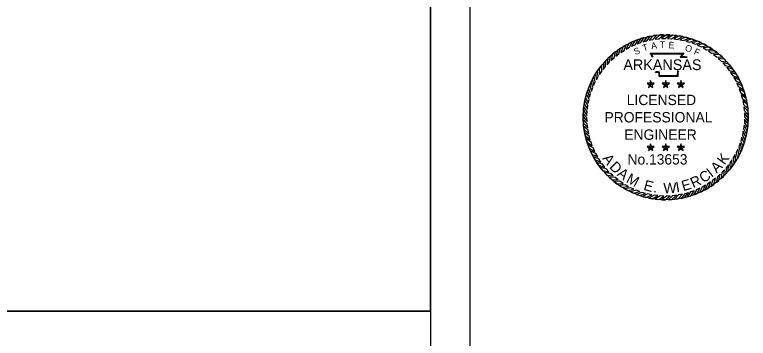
# Model space of a CAD drawing. Extents: x 0 to 19, y -0.6 to 11.2.
# Drawn here: x 13.69 to 19.02, y 5.3 to 7.66 of the extents above; entities that cross this region are included whole.
import ezdxf

# ---------------------------------------------------------------- set-up
doc = ezdxf.new("R2010")
doc.units = 0
for name, color, linetype in [('G-ANNO-STMP', 7, 'Continuous'), ('G-Border-Paper', 7, 'Continuous'), ('G-Border-Sheet', 7, 'Continuous'), ('G-No Plot-Border-1', 7, 'Continuous'), ('G-No Plot-Border-2', 7, 'Continuous'), ('G-No Plot-Stamp-1', 7, 'Continuous'), ('G-No Plot-Stamp-2', 7, 'Continuous')]:
    doc.layers.add(name, color=color, linetype=linetype)

msp = doc.modelspace()

# ---------------------------------------------------------------- linework, layer by layer
at = {"layer": 'G-ANNO-STMP'}
for points in [[(18.2206, 7.4747), (18.1965, 7.4655), (18.1738, 7.4255), (18.1992, 7.437)], [(18.2656, 7.4888), (18.2408, 7.4815), (18.2151, 7.4434), (18.2413, 7.4529)], [(18.3115, 7.4993), (18.2862, 7.494), (18.2576, 7.458), (18.2845, 7.4654)], [(18.3581, 7.5062), (18.3325, 7.5029), (18.3011, 7.4693), (18.3285, 7.4745)], [(18.4051, 7.5094), (18.3793, 7.5081), (18.3454, 7.477), (18.3731, 7.4801)], [(18.4522, 7.5089), (18.4264, 7.5096), (18.3902, 7.4813), (18.418, 7.4822)], [(18.4991, 7.5047), (18.4735, 7.5074), (18.4351, 7.4821), (18.463, 7.4808)], [(18.5456, 7.4968), (18.5202, 7.5016), (18.48, 7.4793), (18.5077, 7.4758)], [(18.5913, 7.4853), (18.5664, 7.4921), (18.5245, 7.473), (18.5518, 7.4674)], [(18.6359, 7.4703), (18.6116, 7.479), (18.5684, 7.4632), (18.5952, 7.4555)], [(18.0942, 7.412), (18.0729, 7.3975), (18.0603, 7.3533), (18.0823, 7.3704)], [(18.1347, 7.4362), (18.1123, 7.4234), (18.0962, 7.3803), (18.1195, 7.3956)], [(18.1769, 7.4572), (18.1536, 7.4461), (18.1341, 7.4044), (18.1585, 7.4179)], [(18.6793, 7.4518), (18.6557, 7.4624), (18.6114, 7.4501), (18.6375, 7.4402)], [(18.721, 7.43), (18.6984, 7.4423), (18.6532, 7.4336), (18.6784, 7.4217)], [(18.7609, 7.4049), (18.7393, 7.419), (18.6936, 7.4138), (18.7178, 7.4)], [(18.0558, 7.3848), (18.0357, 7.3686), (18.0266, 7.3235), (18.0472, 7.3423)], [(18.7987, 7.3768), (18.7783, 7.3926), (18.7323, 7.391), (18.7554, 7.3753)], [(18.8342, 7.3458), (18.8151, 7.3632), (18.7692, 7.3652), (18.7909, 7.3477)], [(17.986, 7.3216), (17.9687, 7.3025), (17.9667, 7.2565), (17.9841, 7.2783)], [(18.0197, 7.3545), (18.0009, 7.3368), (17.9953, 7.2912), (18.0144, 7.3115)], [(18.8672, 7.3122), (18.8495, 7.3309), (18.8038, 7.3365), (18.8242, 7.3175)], [(18.8974, 7.276), (18.8812, 7.2961), (18.8361, 7.3053), (18.8549, 7.2847)], [(17.955, 7.2861), (17.9393, 7.2657), (17.9409, 7.2197), (17.9565, 7.2428)], [(18.9247, 7.2376), (18.9101, 7.2589), (18.8659, 7.2716), (18.883, 7.2496)], [(17.9019, 7.2084), (17.8895, 7.1857), (17.8983, 7.1406), (17.9102, 7.1658)], [(17.9269, 7.2483), (17.9128, 7.2267), (17.918, 7.181), (17.9318, 7.2052)], [(18.9489, 7.1972), (18.936, 7.2196), (18.893, 7.2357), (18.9083, 7.2124)], [(17.88, 7.1666), (17.8695, 7.1431), (17.8818, 7.0988), (17.8916, 7.1248)], [(18.3125, 7.1485), (18.3064, 7.157), (18.2864, 7.157), (18.3026, 7.1453)], [(18.3125, 7.1485), (18.3026, 7.1453), (18.2964, 7.1263), (18.3125, 7.1381)], [(18.3125, 7.1485), (18.3187, 7.157), (18.3125, 7.176), (18.3064, 7.157)], [(18.3125, 7.1485), (18.3225, 7.1453), (18.3386, 7.157), (18.3187, 7.157)], [(18.3125, 7.1485), (18.3125, 7.1381), (18.3286, 7.1263), (18.3225, 7.1453)], [(18.4222, 7.1485), (18.4161, 7.157), (18.3962, 7.157), (18.4123, 7.1453)], [(18.4222, 7.1485), (18.4123, 7.1453), (18.4061, 7.1263), (18.4222, 7.1381)], [(18.4222, 7.1485), (18.4284, 7.157), (18.4222, 7.176), (18.4161, 7.157)], [(18.4222, 7.1485), (18.4322, 7.1453), (18.4483, 7.157), (18.4284, 7.157)], [(18.4222, 7.1485), (18.4222, 7.1381), (18.4384, 7.1263), (18.4322, 7.1453)], [(18.532, 7.1485), (18.5258, 7.157), (18.5059, 7.157), (18.522, 7.1453)], [(18.532, 7.1485), (18.522, 7.1453), (18.5158, 7.1263), (18.532, 7.1381)], [(18.532, 7.1485), (18.5381, 7.157), (18.532, 7.176), (18.5258, 7.157)], [(18.532, 7.1485), (18.5419, 7.1453), (18.5581, 7.157), (18.5381, 7.157)], [(18.532, 7.1485), (18.532, 7.1381), (18.5481, 7.1263), (18.5419, 7.1453)], [(18.9698, 7.155), (18.9588, 7.1783), (18.9171, 7.1977), (18.9305, 7.1733)], [(18.9874, 7.1113), (18.9782, 7.1354), (18.9382, 7.158), (18.9496, 7.1326)], [(17.8615, 7.1233), (17.8529, 7.099), (17.8686, 7.0558), (17.8764, 7.0825)], [(19.0015, 7.0663), (18.9942, 7.0911), (18.9561, 7.1168), (18.9655, 7.0905)], [(17.8465, 7.0786), (17.8398, 7.0537), (17.8588, 7.0119), (17.8645, 7.0392)], [(19.012, 7.0204), (19.0067, 7.0456), (18.9707, 7.0742), (18.978, 7.0474)], [(17.8272, 6.9865), (17.8244, 6.9608), (17.8498, 6.9225), (17.8511, 6.9503)], [(17.835, 7.0329), (17.8303, 7.0076), (17.8526, 6.9674), (17.856, 6.995)], [(19.0188, 6.9738), (19.0155, 6.9993), (18.9819, 7.0307), (18.9871, 7.0033)], [(19.022, 6.9267), (19.0207, 6.9525), (18.9897, 6.9864), (18.9927, 6.9587)], [(17.823, 6.9396), (17.8222, 6.9138), (17.8505, 6.8775), (17.8497, 6.9054)], [(19.0215, 6.8796), (19.0223, 6.9054), (18.994, 6.9417), (18.9948, 6.9138)], [(17.8225, 6.8925), (17.8237, 6.8667), (17.8548, 6.8328), (17.8518, 6.8605)], [(19.0173, 6.8327), (19.0201, 6.8584), (18.9947, 6.8967), (18.9934, 6.8689)], [(17.8256, 6.8454), (17.829, 6.8199), (17.8626, 6.7885), (17.8574, 6.8159)], [(19.0095, 6.7863), (19.0142, 6.8116), (18.9919, 6.8518), (18.9884, 6.8242)], [(17.8325, 6.7988), (17.8378, 6.7736), (17.8738, 6.745), (17.8665, 6.7718)], [(18.998, 6.7406), (19.0047, 6.7655), (18.9856, 6.8073), (18.98, 6.78)], [(17.843, 6.7529), (17.8503, 6.7281), (17.8884, 6.7024), (17.879, 6.7287)], [(18.9645, 6.6526), (18.975, 6.6761), (18.9627, 6.7204), (18.9529, 6.6944)], [(18.9829, 6.6959), (18.9916, 6.7202), (18.9759, 6.7634), (18.9681, 6.7367)], [(17.8571, 6.7079), (17.8663, 6.6838), (17.9063, 6.6612), (17.8949, 6.6866)], [(18.3125, 6.6891), (18.3064, 6.6976), (18.2864, 6.6976), (18.3026, 6.6858)], [(18.3125, 6.6891), (18.3026, 6.6858), (18.2964, 6.6669), (18.3125, 6.6786)], [(18.3125, 6.6891), (18.3187, 6.6976), (18.3125, 6.7165), (18.3064, 6.6976)], [(18.3125, 6.6891), (18.3225, 6.6858), (18.3386, 6.6976), (18.3187, 6.6976)], [(18.3125, 6.6891), (18.3125, 6.6786), (18.3286, 6.6669), (18.3225, 6.6858)], [(18.4222, 6.6891), (18.4161, 6.6976), (18.3962, 6.6976), (18.4123, 6.6858)], [(18.4222, 6.6891), (18.4123, 6.6858), (18.4061, 6.6669), (18.4222, 6.6786)], [(18.4222, 6.6891), (18.4284, 6.6976), (18.4222, 6.7165), (18.4161, 6.6976)], [(18.4222, 6.6891), (18.4322, 6.6858), (18.4483, 6.6976), (18.4284, 6.6976)], [(18.4222, 6.6891), (18.4222, 6.6786), (18.4384, 6.6669), (18.4322, 6.6858)], [(18.532, 6.6891), (18.5258, 6.6976), (18.5059, 6.6976), (18.522, 6.6858)], [(18.532, 6.6891), (18.522, 6.6858), (18.5158, 6.6669), (18.532, 6.6786)], [(18.532, 6.6891), (18.5381, 6.6976), (18.532, 6.7165), (18.5258, 6.6976)], [(18.532, 6.6891), (18.5419, 6.6858), (18.5581, 6.6976), (18.5381, 6.6976)], [(18.532, 6.6891), (18.532, 6.6786), (18.5481, 6.6669), (18.5419, 6.6858)], [(18.9426, 6.6108), (18.955, 6.6335), (18.9462, 6.6786), (18.9343, 6.6534)], [(17.8747, 6.6642), (17.8857, 6.6409), (17.9274, 6.6215), (17.914, 6.6459)], [(17.8956, 6.622), (17.9085, 6.5996), (17.9515, 6.5835), (17.9362, 6.6068)], [(18.9176, 6.5709), (18.9317, 6.5925), (18.9265, 6.6382), (18.9127, 6.614)], [(17.9198, 6.5816), (17.9344, 6.5603), (17.9786, 6.5476), (17.9615, 6.5696)], [(18.8585, 6.4976), (18.8758, 6.5167), (18.8778, 6.5627), (18.8604, 6.5409)], [(18.8895, 6.5331), (18.9052, 6.5535), (18.9036, 6.5995), (18.888, 6.5764)], [(17.9471, 6.5432), (17.9633, 6.5231), (18.0083, 6.5139), (17.9896, 6.5345)], [(17.9773, 6.507), (17.995, 6.4883), (18.0407, 6.4827), (18.0203, 6.5017)], [(18.8248, 6.4647), (18.8436, 6.4824), (18.8492, 6.528), (18.8301, 6.5077)], [(18.0103, 6.4734), (18.0294, 6.456), (18.0753, 6.454), (18.0536, 6.4715)], [(18.7503, 6.4072), (18.7716, 6.4217), (18.7842, 6.4659), (18.7622, 6.4488)], [(18.7887, 6.4344), (18.8088, 6.4506), (18.8179, 6.4957), (18.7973, 6.4769)], [(18.0458, 6.4424), (18.0662, 6.4266), (18.1122, 6.4282), (18.0891, 6.4439)], [(18.0836, 6.4143), (18.1052, 6.4002), (18.1509, 6.4054), (18.1267, 6.4192)], [(18.6676, 6.362), (18.6909, 6.3731), (18.7104, 6.4148), (18.6859, 6.4013)], [(18.7098, 6.383), (18.7322, 6.3958), (18.7483, 6.4389), (18.725, 6.4236)], [(18.1235, 6.3892), (18.1461, 6.3769), (18.1913, 6.3856), (18.166, 6.3975)], [(18.1652, 6.3674), (18.1888, 6.3568), (18.2331, 6.3691), (18.207, 6.379)], [(18.2086, 6.3489), (18.2329, 6.3402), (18.2761, 6.356), (18.2493, 6.3637)], [(18.2532, 6.3339), (18.2781, 6.3271), (18.32, 6.3462), (18.2927, 6.3518)], [(18.4864, 6.313), (18.512, 6.3163), (18.5434, 6.3499), (18.516, 6.3447)], [(18.533, 6.3199), (18.5583, 6.3252), (18.5869, 6.3612), (18.56, 6.3538)], [(18.5789, 6.3304), (18.6037, 6.3377), (18.6294, 6.3758), (18.6032, 6.3663)], [(18.6239, 6.3445), (18.648, 6.3537), (18.6707, 6.3937), (18.6453, 6.3822)], [(18.2989, 6.3224), (18.3243, 6.3176), (18.3645, 6.3399), (18.3368, 6.3434)], [(18.3454, 6.3145), (18.371, 6.3118), (18.4094, 6.3371), (18.3815, 6.3384)], [(18.3923, 6.3103), (18.4181, 6.3096), (18.4543, 6.3379), (18.4265, 6.337)], [(18.4394, 6.3098), (18.4652, 6.3111), (18.4991, 6.3422), (18.4714, 6.3391)]]:
    msp.add_lwpolyline(points, close=True, dxfattribs=at)
for points in [[(18.3261, 7.3451), (18.3121, 7.3754), (18.5542, 7.3755), (18.5339, 7.3501), (18.5504, 7.3503), (18.5641, 7.3505), (18.5778, 7.349)], [(18.3296, 7.3467), (18.3181, 7.3716), (18.5462, 7.3717), (18.5259, 7.3462), (18.5504, 7.3465), (18.5639, 7.3467), (18.5774, 7.3452)], [(18.516, 7.2437), (18.5119, 7.2403), (18.5105, 7.2353), (18.5091, 7.2227), (18.5091, 7.206), (18.374, 7.206), (18.374, 7.2286), (18.374, 7.2336), (18.3686, 7.2353), (18.3493, 7.2353), (18.3459, 7.2405)], [(18.5136, 7.2466), (18.5085, 7.2425), (18.5067, 7.236), (18.5053, 7.223), (18.5053, 7.2099), (18.3779, 7.2099), (18.3779, 7.2286), (18.3779, 7.2365), (18.3691, 7.2391), (18.3514, 7.2391), (18.3491, 7.2426)]]:
    msp.add_lwpolyline(points, dxfattribs=at)
at = {"layer": 'G-Border-Paper'}
msp.add_lwpolyline([(17, 11), (0, 11), (0, 0), (17, 0)], close=True, dxfattribs=at)
at = {"layer": 'G-Border-Sheet'}
msp.add_line((16.7116, 5.5), (16.7116, 10.7116), dxfattribs=at)
msp.add_lwpolyline([(0.758, 5.5), (16.7116, 5.5), (16.7116, 0.2884), (0.758, 0.2884)], close=True, dxfattribs=at)
at = {"layer": 'G-No Plot-Border-1'}
msp.add_lwpolyline([(0.758, 5.5), (0.758, 10.7116), (13.7281, 10.7116), (13.7281, 10.2161), (14.7206, 10.2161), (14.8024, 10.2161), (15.4366, 10.2161), (15.4366, 8.7411), (16.7116, 8.7411), (16.7116, 5.5)], close=True, dxfattribs=at)
at = {"layer": 'G-No Plot-Border-2'}
msp.add_lwpolyline([(0.758, 5.5), (0.758, 10.7116), (12.3781, 10.7116), (12.3781, 9.2366), (13.7281, 9.2366), (13.7281, 10.2161), (14.7206, 10.2161), (14.9256, 10.2161), (16.7116, 10.2161), (16.7116, 5.5)], close=True, dxfattribs=at)
at = {"layer": 'G-No Plot-Stamp-1'}
msp.add_circle((18.4222, 6.9096), 0.6, dxfattribs=at)
at = {"layer": 'G-No Plot-Stamp-2'}
msp.add_circle((18.4222, 6.9096), 0.6, dxfattribs=at)

# ---------------------------------------------------------------- texts
at = {"layer": 'G-ANNO-STMP'}
for s, height, rotation, p in [('S', 0.0477, 19.7726, (18.2001, 7.361)), ('T', 0.0477, 16.9015, (18.2608, 7.3882)), ('A', 0.0477, 8.6788, (18.3187, 7.4034)), ('T', 0.0477, 1.4789, (18.3804, 7.4129)), ('E', 0.0477, 356.672, (18.4415, 7.4114)), ('O', 0.0477, 341.2218, (18.5574, 7.395)), ('F', 0.0477, 335.3628, (18.6218, 7.3699)), ('A', 0.0754, 305.982, (17.958, 6.6093)), ('K', 0.0754, 53.8471, (18.8495, 6.5585)), ('D', 0.0754, 314.3022, (18.0075, 6.5441)), ('A', 0.0754, 45.185, (18.7929, 6.4994)), ('A', 0.0754, 322.6223, (18.0634, 6.4889)), ('C', 0.0754, 32.1396, (18.695, 6.4289)), ('I', 0.0754, 38.4057, (18.7549, 6.4687)), ('M', 0.0754, 331.7969, (18.1293, 6.4402)), ('E', 0.0754, 345.2782, (18.2564, 6.3823)), ('E', 0.0754, 16.0125, (18.5491, 6.3716)), ('R', 0.0754, 24.1616, (18.6211, 6.3937)), ('W', 0.0754, 2.1127, (18.4063, 6.3565)), ('I', 0.0754, 9.5753, (18.5011, 6.363)), ('.', 0.0754, 350.8583, (18.3296, 6.3653))]:
    msp.add_text(s, height=height, rotation=rotation, dxfattribs=at).set_placement(p)
for s, height, p in [('ARKANSAS', 0.07792, (18.1143, 7.2524)), ('LICENSED', 0.07543, (18.1385, 6.998)), ('PROFESSIONAL', 0.075433, (17.9768, 6.8719)), ('ENGINEER', 0.07543, (18.1205, 6.7457)), ('No.13653', 0.07514, (18.1443, 6.5659))]:
    msp.add_text(s, height=height, dxfattribs=at).set_placement(p)

doc.saveas('drawing.dxf')
